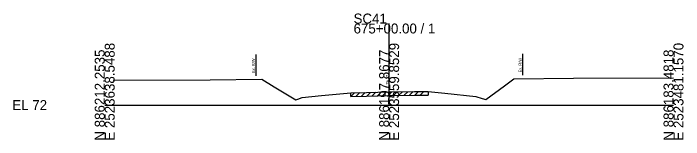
# Model space of a CAD drawing. Extents: x -26 to 183, y -10 to 24021.
# Drawn here: x -25.7 to 162.8, y 7490.3 to 7525.8 of the extents above; entities that cross this region are included whole.
import ezdxf

# ---------------------------------------------------------------- set-up
doc = ezdxf.new("R2010")
doc.units = 0
for name, color, linetype in [('RD_GPK_XS_Cell', 7, 'Continuous'), ('RD_XS_ExGround', 7, 'Continuous'), ('RD_XS_ExPaveRet', 7, 'Continuous'), ('RD_XS_ExRW', 7, 'Continuous'), ('RD_XS_TX_Elev_EX', 7, 'Continuous')]:
    doc.layers.add(name, color=color, linetype=linetype)

msp = doc.modelspace()

# ---------------------------------------------------------------- linework, layer by layer
at = {"layer": 'RD_GPK_XS_Cell'}
for p, q in [((80, 7500), (80, 7522.92)), ((0, 7500), (80, 7500)), ((80, 7500), (160, 7500))]:
    msp.add_line(p, q, dxfattribs=at)
at = {"layer": 'RD_XS_ExGround'}
for p, q in [((112.5, 7505.44), (115.12, 7507.38)), ((115.12, 7507.38), (131.88, 7507.53)), ((131.88, 7507.53), (160, 7507.64)), ((2.41, 7507.05), (29.67, 7507.14)), ((29.67, 7507.14), (44.2, 7507.27)), ((44.2, 7507.27), (47.64, 7505.17)), ((47.64, 7505.17), (53.78, 7501.48)), ((73.68, 7503.55), (80, 7503.72)), ((80, 7503.72), (80.66, 7503.74)), ((80.66, 7503.74), (87.18, 7503.79)), ((87.18, 7503.79), (90.95, 7503.82)), ((90.95, 7503.82), (95.7, 7503.33)), ((107.25, 7501.56), (112.5, 7505.44)), ((54.33, 7501.71), (55.57, 7502.17)), ((55.57, 7502.17), (61, 7502.67)), ((61, 7502.67), (69.25, 7503.43)), ((69.25, 7503.43), (73.68, 7503.55)), ((95.7, 7503.33), (104.35, 7502.42)), ((104.35, 7502.42), (106.19, 7501.85)), ((106.19, 7501.85), (107.25, 7501.56)), ((53.78, 7501.48), (54.33, 7501.71))]:
    msp.add_line(p, q, dxfattribs=at)
at = {"layer": 'RD_XS_ExPaveRet'}
for p, q in [((75.25, 7502.59), (76.28, 7503.62)), ((76.75, 7502.63), (77.78, 7503.66)), ((78.25, 7502.67), (79.28, 7503.7)), ((79.75, 7502.71), (80.77, 7503.74)), ((81.25, 7502.74), (82.26, 7503.75)), ((82.75, 7502.75), (83.76, 7503.76)), ((84.25, 7502.77), (85.26, 7503.77)), ((85.75, 7502.78), (86.76, 7503.79)), ((87.25, 7502.79), (88.26, 7503.8)), ((88.75, 7502.8), (89.76, 7503.81)), ((90.95, 7503.82), (90.95, 7502.82)), ((69.25, 7502.43), (70.28, 7503.45)), ((69.25, 7502.43), (69.25, 7503.43)), ((69.25, 7502.43), (73.68, 7502.55)), ((70.75, 7502.47), (71.78, 7503.5)), ((72.25, 7502.51), (73.28, 7503.54)), ((73.68, 7502.55), (80, 7502.72)), ((73.75, 7502.55), (74.78, 7503.58)), ((80, 7502.72), (80.66, 7502.74)), ((80.66, 7502.74), (87.18, 7502.79)), ((87.18, 7502.79), (90.95, 7502.82))]:
    msp.add_line(p, q, dxfattribs=at)
at = {"layer": 'RD_XS_ExRW'}
for p, q in [((42.5, 7514.26), (42.5, 7508.26)), ((117.5, 7514.41), (117.5, 7508.41))]:
    msp.add_line(p, q, dxfattribs=at)

# ---------------------------------------------------------------- texts
at = {"layer": 'RD_GPK_XS_Cell'}
for s, p in [('SC41', (70, 7522.92)), ('675+00.00 / 1', (70, 7520.12)), ('EL 72', (-26, 7498.6))]:
    msp.add_text(s, height=2.8, dxfattribs=at).set_placement(p)
for s, p in [('E 2523638.5488', (2.8, 7490)), ('E 2523559.8529', (82.8, 7490)), ('E 2523481.1570', (162.8, 7490)), ('N 886212.2535', (0, 7490)), ('N 886197.8677', (80, 7490)), ('N 886183.4818', (160, 7490))]:
    msp.add_text(s, height=2.8, rotation=90, dxfattribs=at).set_placement(p)
at = {"layer": 'RD_XS_ExRW'}
for p in [(117.25, 7509.19), (42.25, 7509.04)]:
    msp.add_text('Ex. R/W ', height=0.8, rotation=90, dxfattribs=at).set_placement(p)
at = {"layer": 'RD_XS_TX_Elev_EX'}
msp.add_text('75.72', height=0.8, rotation=90, dxfattribs=at).set_placement((79.9, 7505.72))

doc.saveas('drawing.dxf')
